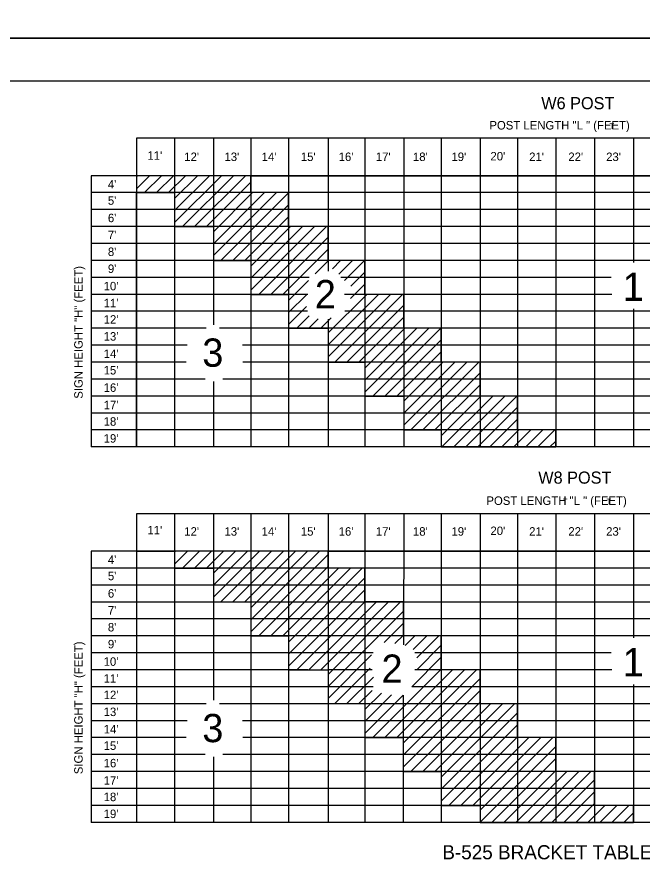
# Model space of a CAD drawing. Extents: x 637580 to 641008, y 294594 to 295782.
# Drawn here: x 639503.7 to 639725, y 294891.9 to 295195.1 of the extents above; entities that cross this region are included whole.
import ezdxf

# ---------------------------------------------------------------- set-up
doc = ezdxf.new("R2010")
doc.units = 0
for name, color, linetype in [('1', 7, 'Continuous'), ('2', 7, 'Continuous'), ('PLT-BNDY', 7, 'Continuous')]:
    doc.layers.add(name, color=color, linetype=linetype)

msp = doc.modelspace()

# ---------------------------------------------------------------- linework, layer by layer
at = {"layer": '1'}
msp.add_line((639302.31, 295172.63), (640088.31, 295172.63), dxfattribs=at)
at = {"layer": '2'}
for p, q in [((639866.29, 295152.27), (639545.88, 295152.27)), ((639545.88, 295152.27), (639545.88, 295043.01)), ((639559.39, 295152.27), (639559.39, 295043.01)), ((639573.15, 295152.27), (639573.15, 295086.26)), ((639586.4, 295152.27), (639586.4, 295043.01)), ((639599.66, 295152.27), (639599.66, 295043.01)), ((639613.67, 295152.27), (639613.67, 295105.22)), ((639626.67, 295152.27), (639626.67, 295043.01)), ((639640.43, 295152.27), (639640.43, 295043.01)), ((639653.69, 295152.27), (639653.69, 295043.01)), ((639667.45, 295152.27), (639667.45, 295043.01)), ((639680.7, 295152.27), (639680.7, 295043.01)), ((639694.21, 295152.27), (639694.21, 295043.01)), ((639707.97, 295152.27), (639707.97, 295043.01)), ((639721.72, 295152.27), (639721.72, 295108.29)), ((639529.84, 295139.01), (639529.84, 295043.01)), ((639866.29, 295139.01), (639529.84, 295139.01)), ((639545.88, 295139.01), (639545.88, 295133.01)), ((639551.38, 295139.01), (639545.88, 295139.01)), ((639545.88, 295138.6), (639546.29, 295139.01)), ((639545.88, 295134.36), (639550.53, 295139.01)), ((639548.78, 295133.01), (639554.78, 295139.01)), ((639586.4, 295139.01), (639551.38, 295139.01)), ((639553.02, 295133.01), (639559.02, 295139.01)), ((639557.26, 295133.01), (639563.26, 295139.01)), ((639559.39, 295130.9), (639567.5, 295139.01)), ((639559.39, 295126.65), (639571.75, 295139.01)), ((639559.39, 295122.41), (639575.99, 295139.01)), ((639562.23, 295121.01), (639580.23, 295139.01)), ((639566.47, 295121.01), (639584.47, 295139.01)), ((639586.4, 295133.01), (639586.4, 295139.01)), ((639586.4, 295139.01), (639827.27, 295139.01)), ((639570.72, 295121.01), (639586.4, 295136.7)), ((639827.27, 295133.01), (639529.84, 295133.01)), ((639545.88, 295043.01), (639545.88, 295133.01)), ((639545.88, 295133.01), (639559.39, 295133.01)), ((639545.88, 295133.01), (639559.39, 295133.01)), ((639559.39, 295133.01), (639559.39, 295121.01)), ((639559.39, 295133.01), (639559.39, 295121.01)), ((639573.15, 295119.2), (639586.96, 295133.01)), ((639573.15, 295114.95), (639591.2, 295133.01)), ((639573.15, 295110.71), (639595.44, 295133.01)), ((639575.69, 295109.01), (639599.66, 295132.98)), ((639599.66, 295133.01), (639586.4, 295133.01)), ((639599.66, 295121.01), (639599.66, 295133.01)), ((639840.28, 295127.01), (639529.84, 295127.01)), ((639579.93, 295109.01), (639599.66, 295128.74)), ((639584.17, 295109.01), (639599.66, 295124.5)), ((639840.28, 295121.01), (639529.84, 295121.01)), ((639559.39, 295121.01), (639573.15, 295121.01)), ((639559.39, 295121.01), (639573.15, 295121.01)), ((639573.15, 295121.01), (639573.15, 295109.01)), ((639573.15, 295121.01), (639573.15, 295109.01)), ((639586.4, 295107), (639600.41, 295121.01)), ((639586.4, 295102.75), (639604.66, 295121.01)), ((639586.4, 295098.51), (639608.9, 295121.01)), ((639589.14, 295097.01), (639613.14, 295121.01)), ((639613.67, 295121.01), (639599.66, 295121.01)), ((639613.67, 295109.01), (639613.67, 295121.01)), ((639853.28, 295115.01), (639529.84, 295115.01)), ((639593.39, 295097.01), (639613.67, 295117.29)), ((639597.63, 295097.01), (639613.67, 295113.05)), ((639853.28, 295109.01), (639529.84, 295109.01)), ((639573.15, 295109.01), (639586.4, 295109.01)), ((639573.15, 295109.01), (639586.4, 295109.01)), ((639586.4, 295109.01), (639586.4, 295097.01)), ((639586.4, 295109.01), (639586.4, 295097.01)), ((639609.14, 295104.28), (639613.87, 295109.01)), ((639626.67, 295109.01), (639613.67, 295109.01)), ((639615.2, 295106.09), (639618.11, 295109.01)), ((639617.45, 295104.1), (639622.36, 295109.01)), ((639619.51, 295101.92), (639626.6, 295109.01)), ((639626.67, 295097.01), (639626.67, 295109.01)), ((639607.01, 295103.01), (639529.84, 295103.01)), ((639713.86, 295103.01), (639618.23, 295103.01)), ((639621.73, 295099.9), (639626.67, 295104.84)), ((639599.66, 295094.8), (639606.72, 295101.86)), ((639621.58, 295095.51), (639626.67, 295100.6)), ((639606.46, 295097.01), (639529.84, 295097.01)), ((639586.4, 295097.01), (639599.66, 295097.01)), ((639586.4, 295097.01), (639599.66, 295097.01)), ((639599.66, 295097.01), (639599.66, 295085.01)), ((639599.66, 295097.01), (639599.66, 295085.01)), ((639599.66, 295090.56), (639606.11, 295097.01)), ((639613.67, 295083.35), (639627.33, 295097.01)), ((639613.67, 295079.11), (639631.57, 295097.01)), ((639613.67, 295074.86), (639635.81, 295097.01)), ((639616.05, 295073.01), (639640.05, 295097.01)), ((639714.04, 295097.01), (639619.44, 295097.01)), ((639640.43, 295097.01), (639626.67, 295097.01)), ((639640.43, 295085.01), (639640.43, 295097.01)), ((639606.35, 295091.01), (639529.84, 295091.01)), ((639599.66, 295086.31), (639606.09, 295092.74)), ((639866.29, 295091.01), (639619.55, 295091.01)), ((639620.3, 295073.01), (639640.43, 295093.14)), ((639721.72, 295091.85), (639721.72, 295043.01)), ((639602.6, 295085.01), (639607.03, 295089.44)), ((639606.84, 295085.01), (639610.13, 295088.3)), ((639611.08, 295085.01), (639614.79, 295088.71)), ((639613.67, 295088.28), (639613.67, 295043.01)), ((639624.54, 295073.01), (639640.43, 295088.9)), ((639570.59, 295085.01), (639529.84, 295085.01)), ((639866.29, 295085.01), (639575.26, 295085.01)), ((639599.66, 295085.01), (639613.67, 295085.01)), ((639599.66, 295085.01), (639613.67, 295085.01)), ((639613.67, 295085.01), (639613.67, 295073.01)), ((639613.67, 295085.01), (639613.67, 295073.01)), ((639626.67, 295070.9), (639640.78, 295085.01)), ((639626.67, 295066.66), (639645.02, 295085.01)), ((639626.67, 295062.42), (639649.27, 295085.01)), ((639629.51, 295061.01), (639653.51, 295085.01)), ((639653.69, 295085.01), (639640.43, 295085.01)), ((639653.69, 295073.01), (639653.69, 295085.01)), ((639563.85, 295079.01), (639529.84, 295079.01)), ((639866.29, 295079.01), (639583.36, 295079.01)), ((639633.75, 295061.01), (639653.69, 295080.94)), ((639638, 295061.01), (639653.69, 295076.7)), ((639563.44, 295073.01), (639529.84, 295073.01)), ((639866.29, 295073.01), (639583.5, 295073.01)), ((639613.67, 295073.01), (639626.67, 295073.01)), ((639613.67, 295073.01), (639626.67, 295073.01)), ((639626.67, 295073.01), (639626.67, 295061.01)), ((639626.67, 295073.01), (639626.67, 295061.01)), ((639640.43, 295059.2), (639654.24, 295073.01)), ((639640.43, 295054.96), (639658.48, 295073.01)), ((639640.43, 295050.72), (639662.72, 295073.01)), ((639642.97, 295049.01), (639666.97, 295073.01)), ((639667.45, 295073.01), (639653.69, 295073.01)), ((639667.45, 295061.01), (639667.45, 295073.01)), ((639647.21, 295049.01), (639667.45, 295069.25)), ((639570.17, 295067.01), (639529.84, 295067.01)), ((639573.15, 295066.19), (639573.15, 295043.01)), ((639866.29, 295067.01), (639576.49, 295067.01)), ((639651.45, 295049.01), (639667.45, 295065)), ((639866.29, 295061.01), (639529.84, 295061.01)), ((639626.67, 295061.01), (639640.43, 295061.01)), ((639626.67, 295061.01), (639640.43, 295061.01)), ((639640.43, 295061.01), (639640.43, 295049.01)), ((639640.43, 295061.01), (639640.43, 295049.01)), ((639653.69, 295047), (639667.69, 295061.01)), ((639653.94, 295043.01), (639671.94, 295061.01)), ((639658.18, 295043.01), (639676.18, 295061.01)), ((639662.42, 295043.01), (639680.42, 295061.01)), ((639680.7, 295061.01), (639667.45, 295061.01)), ((639680.7, 295049.01), (639680.7, 295061.01)), ((639666.66, 295043.01), (639680.7, 295057.05)), ((639866.29, 295055.01), (639529.84, 295055.01)), ((639670.91, 295043.01), (639680.7, 295052.8)), ((639866.29, 295049.01), (639529.84, 295049.01)), ((639640.43, 295049.01), (639653.69, 295049.01)), ((639640.43, 295049.01), (639653.69, 295049.01)), ((639653.69, 295049.01), (639653.69, 295043.01)), ((639653.69, 295049.01), (639653.69, 295043.01)), ((639675.15, 295043.01), (639681.15, 295049.01)), ((639679.39, 295043.01), (639685.39, 295049.01)), ((639694.21, 295049.01), (639680.7, 295049.01)), ((639683.64, 295043.01), (639689.64, 295049.01)), ((639687.88, 295043.01), (639693.88, 295049.01)), ((639694.21, 295043.01), (639694.21, 295049.01)), ((639692.12, 295043.01), (639694.21, 295045.1)), ((639866.29, 295043.01), (639529.84, 295043.01)), ((639653.69, 295043.01), (639545.88, 295043.01)), ((639653.69, 295043.01), (639694.21, 295043.01)), ((639866.29, 295043.01), (639694.21, 295043.01)), ((639866.29, 295019.39), (639545.88, 295019.39)), ((639545.88, 295019.39), (639545.88, 294910.13)), ((639559.39, 295019.39), (639559.39, 294910.13)), ((639573.15, 295019.39), (639573.15, 294953.39)), ((639586.4, 295019.39), (639586.4, 294910.13)), ((639599.66, 295019.39), (639599.66, 294910.13)), ((639613.67, 295019.39), (639613.67, 294910.13)), ((639626.67, 295019.39), (639626.67, 294910.13)), ((639640.43, 295019.39), (639640.33, 294973.02)), ((639653.69, 295019.39), (639653.69, 294910.13)), ((639667.45, 295019.39), (639667.45, 294910.13)), ((639680.7, 295019.39), (639680.7, 294910.13)), ((639694.21, 295019.39), (639694.21, 294910.13)), ((639707.97, 295019.39), (639707.97, 294910.13)), ((639721.72, 295019.39), (639721.72, 294975.41)), ((639529.84, 295006.13), (639529.84, 294910.13)), ((639866.29, 295006.13), (639529.84, 295006.13)), ((639545.88, 295006.13), (639559.39, 295006.13)), ((639545.88, 295005.73), (639546.29, 295006.13)), ((639559.4, 295006.13), (639559.4, 295000.11)), ((639564.96, 295006.13), (639559.4, 295006.13)), ((639559.4, 295005.79), (639559.74, 295006.13)), ((639559.4, 295001.55), (639563.99, 295006.13)), ((639562.21, 295000.11), (639568.23, 295006.13)), ((639613.67, 295006.13), (639564.96, 295006.13)), ((639566.45, 295000.11), (639572.47, 295006.13)), ((639570.69, 295000.11), (639576.72, 295006.13)), ((639573.13, 294998.31), (639580.96, 295006.13)), ((639573.13, 294994.07), (639585.2, 295006.13)), ((639573.13, 294989.82), (639589.44, 295006.13)), ((639575.69, 294988.14), (639593.69, 295006.13)), ((639579.94, 294988.14), (639597.93, 295006.13)), ((639584.18, 294988.14), (639602.17, 295006.13)), ((639586.4, 294986.12), (639606.41, 295006.13)), ((639586.4, 294981.88), (639610.66, 295006.13)), ((639613.66, 295000.13), (639613.67, 295006.13)), ((639613.67, 295006.13), (639827.27, 295006.13)), ((639586.4, 294977.63), (639613.66, 295004.9)), ((639827.27, 295000.13), (639529.84, 295000.13)), ((639559.4, 295000.11), (639573.13, 295000.11)), ((639573.13, 295000.11), (639573.13, 294988.14)), ((639589.14, 294976.13), (639613.64, 295000.63)), ((639593.38, 294976.13), (639617.31, 295000.06)), ((639597.63, 294976.13), (639621.55, 295000.06)), ((639599.68, 294973.94), (639625.79, 295000.05)), ((639626.64, 295000.13), (639613.66, 295000.13)), ((639626.67, 294988.14), (639626.64, 295000.13)), ((639599.68, 294969.7), (639626.7, 294996.72)), ((639840.28, 294994.13), (639529.84, 294994.13)), ((639599.68, 294965.45), (639626.68, 294992.46)), ((639840.28, 294988.13), (639529.84, 294988.13)), ((639573.13, 294988.14), (639586.4, 294988.14)), ((639586.4, 294988.14), (639586.4, 294976.13)), ((639602.57, 294964.11), (639626.67, 294988.2)), ((639606.82, 294964.11), (639630.85, 294988.14)), ((639611.06, 294964.11), (639635.09, 294988.14)), ((639613.66, 294962.46), (639639.34, 294988.14)), ((639640.36, 294988.15), (639626.67, 294988.14)), ((639640.36, 294976.13), (639640.36, 294988.15)), ((639613.66, 294958.22), (639640.36, 294984.93)), ((639853.28, 294982.13), (639529.84, 294982.13)), ((639633.46, 294973.79), (639640.36, 294980.68)), ((639853.28, 294976.13), (639529.84, 294976.13)), ((639586.4, 294976.13), (639599.68, 294976.13)), ((639599.68, 294976.13), (639599.68, 294964.11)), ((639637.33, 294973.41), (639640.36, 294976.44)), ((639653.68, 294976.13), (639640.36, 294976.13)), ((639640.89, 294972.73), (639644.32, 294976.15)), ((639643.75, 294971.34), (639648.56, 294976.15)), ((639645.05, 294968.4), (639652.8, 294976.15)), ((639653.68, 294964.11), (639653.68, 294976.13)), ((639645.02, 294964.13), (639653.7, 294972.81)), ((639613.67, 294970.13), (639529.84, 294970.13)), ((639613.66, 294953.98), (639629.09, 294969.41)), ((639629.63, 294970.13), (639613.67, 294970.13)), ((639713.86, 294970.13), (639644.42, 294970.13)), ((639643.27, 294958.13), (639653.7, 294968.56)), ((639606.46, 294964.13), (639529.84, 294964.13)), ((639599.68, 294964.11), (639613.66, 294964.11)), ((639613.66, 294964.11), (639613.66, 294952.18)), ((639629.25, 294964.13), (639613.67, 294964.13)), ((639616.1, 294952.18), (639628.59, 294964.67)), ((639629.52, 294940.14), (639653.7, 294964.32)), ((639633.76, 294940.14), (639657.71, 294964.09)), ((639638.01, 294940.14), (639661.95, 294964.09)), ((639640.28, 294938.17), (639666.2, 294964.09)), ((639714.04, 294964.13), (639644.42, 294964.13)), ((639667.45, 294964.11), (639653.68, 294964.11)), ((639667.46, 294952.11), (639667.45, 294964.11)), ((639620.34, 294952.18), (639629.7, 294961.53)), ((639640.28, 294933.93), (639667.46, 294961.11)), ((639613.67, 294958.13), (639529.84, 294958.13)), ((639629.6, 294958.13), (639613.67, 294958.13)), ((639866.29, 294958.13), (639643.27, 294958.13)), ((639721.72, 294958.97), (639721.72, 294910.13)), ((639624.58, 294952.18), (639629.28, 294956.87)), ((639626.69, 294950.04), (639632.53, 294955.88)), ((639626.69, 294945.8), (639636.15, 294955.26)), ((639626.69, 294941.55), (639640.29, 294955.16)), ((639640.29, 294955.16), (639640.19, 294910.13)), ((639640.28, 294929.69), (639667.46, 294956.87)), ((639570.59, 294952.13), (639529.84, 294952.13)), ((639866.29, 294952.13), (639575.26, 294952.13)), ((639613.66, 294952.18), (639626.69, 294952.18)), ((639626.69, 294952.18), (639626.69, 294940.14)), ((639642.97, 294928.13), (639667.46, 294952.63)), ((639647.21, 294928.13), (639671.19, 294952.11)), ((639651.45, 294928.13), (639675.43, 294952.11)), ((639653.69, 294926.13), (639679.67, 294952.11)), ((639680.71, 294952.11), (639667.46, 294952.11)), ((639680.71, 294940.15), (639680.71, 294952.11)), ((639653.69, 294921.88), (639680.71, 294948.91)), ((639563.85, 294946.13), (639529.84, 294946.13)), ((639866.29, 294946.13), (639583.36, 294946.13)), ((639653.69, 294917.64), (639680.71, 294944.67)), ((639563.44, 294940.13), (639529.84, 294940.13)), ((639866.29, 294940.13), (639583.5, 294940.13)), ((639626.69, 294940.14), (639640.28, 294940.14)), ((639640.28, 294940.14), (639640.28, 294928.13)), ((639656.44, 294916.15), (639680.71, 294940.42)), ((639660.68, 294916.15), (639684.68, 294940.15)), ((639664.92, 294916.15), (639688.93, 294940.15)), ((639667.45, 294914.43), (639693.17, 294940.16)), ((639694.21, 294940.13), (639680.71, 294940.15)), ((639694.22, 294928.14), (639694.21, 294940.13)), ((639667.45, 294910.19), (639694.24, 294936.98)), ((639570.17, 294934.13), (639529.84, 294934.13)), ((639573.15, 294933.32), (639573.15, 294910.13)), ((639866.29, 294934.13), (639576.49, 294934.13)), ((639671.63, 294910.13), (639694.25, 294932.75)), ((639866.29, 294928.13), (639529.84, 294928.13)), ((639640.28, 294928.13), (639653.69, 294928.13)), ((639653.69, 294928.13), (639653.69, 294916.15)), ((639675.88, 294910.13), (639694.21, 294928.47)), ((639680.12, 294910.13), (639698.11, 294928.13)), ((639684.36, 294910.13), (639702.35, 294928.12)), ((639688.6, 294910.13), (639706.58, 294928.11)), ((639694.29, 294928.13), (639694.22, 294928.14)), ((639707.96, 294928.14), (639694.29, 294928.13)), ((639707.97, 294916.13), (639707.96, 294928.14)), ((639692.84, 294910.13), (639707.95, 294925.24)), ((639866.29, 294922.13), (639529.84, 294922.13)), ((639697.09, 294910.13), (639707.93, 294920.98)), ((639866.29, 294916.13), (639529.84, 294916.13)), ((639653.69, 294916.15), (639667.45, 294916.15)), ((639667.45, 294916.15), (639667.45, 294910.13)), ((639701.33, 294910.13), (639707.97, 294916.77)), ((639705.57, 294910.13), (639711.6, 294916.15)), ((639709.81, 294910.13), (639715.84, 294916.15)), ((639714.05, 294910.13), (639720.06, 294916.13)), ((639718.3, 294910.13), (639721.72, 294913.55)), ((639866.29, 294910.13), (639529.84, 294910.13)), ((639667.45, 294910.13), (639545.88, 294910.13)), ((639667.45, 294910.13), (639721.72, 294910.13)), ((639866.29, 294910.13), (639721.72, 294910.13))]:
    msp.add_line(p, q, dxfattribs=at)
msp.add_lwpolyline([(639721.72, 294910.13), (639721.72, 294910.18), (639721.72, 294916.14), (639707.97, 294916.13)], dxfattribs=at)
at = {"layer": 'PLT-BNDY'}
for points in [[(639262.31, 295781.63), (640103.31, 295781.63), (640103.31, 295187.63), (639262.31, 295187.63)], [(639262.31, 295187.63), (640103.31, 295187.63), (640103.31, 294593.63), (639262.31, 294593.63)]]:
    msp.add_lwpolyline(points, close=True, dxfattribs=at)

# ---------------------------------------------------------------- texts
at = {"layer": '2'}
for s, height, p in [('W6 POST', 4.3, (639689.09, 295162.53)), ('POST LENGTH "L " (FEET)', 3, (639670.74, 295155.36)), ('T', 2, (639713.26, 295155.53)), ("11'", 3, (639549.76, 295144.65)), ("12'", 3, (639562.8, 295144.2)), ("13'", 3, (639577.03, 295144.2)), ("14'", 3, (639590.17, 295144.2)), ("15'", 3, (639604.03, 295144.2)), ("16'", 3, (639617.42, 295144.2)), ("17'", 3, (639630.56, 295144.2)), ("18'", 3, (639643.7, 295144.2)), ("19'", 3, (639657.32, 295144.2)), ("20'", 3, (639671.11, 295144.41)), ("21'", 3, (639684.81, 295144.2)), ("22'", 3, (639698.67, 295144.2)), ("23'", 3, (639712.05, 295144.2)), ("4'", 3, (639535.78, 295134.48)), ("5'", 3, (639535.78, 295128.72)), ("6'", 3, (639535.78, 295122.56)), ("7'", 3, (639535.78, 295116.57)), ("8'", 3, (639535.78, 295110.58)), ("9'", 3, (639535.78, 295104.59)), ('1', 10, (639717.89, 295094.72)), ("10'", 3, (639534.28, 295098.43)), ('2', 10, (639609, 295092.1)), ("11'", 3, (639534.28, 295092.44)), ("12'", 3, (639534.28, 295086.63)), ("13'", 3, (639534.28, 295080.64)), ('3', 10, (639569.18, 295071.39)), ("14'", 3, (639534.28, 295074.47)), ("15'", 3, (639534.28, 295068.66)), ("16'", 3, (639534.28, 295062.5)), ("17'", 3, (639534.28, 295056.33)), ("18'", 3, (639534.28, 295050.52)), ("19'", 3, (639534.28, 295044.53)), ('W8 POST', 4.3, (639688.03, 295030.01)), ('POST LENGTH "L " (FEET)', 3, (639669.69, 295022.49)), ('T', 2, (639696.71, 295022.66)), ('T', 2, (639712.21, 295022.66)), ("11'", 3, (639549.76, 295012.07)), ("12'", 3, (639562.8, 295011.61)), ("13'", 3, (639577.03, 295011.61)), ("14'", 3, (639590.17, 295011.61)), ("15'", 3, (639604.03, 295011.61)), ("16'", 3, (639617.42, 295011.61)), ("17'", 3, (639630.56, 295011.61)), ("18'", 3, (639643.7, 295011.61)), ("19'", 3, (639657.32, 295011.61)), ("20'", 3, (639671.11, 295011.83)), ("21'", 3, (639684.81, 295011.61)), ("22'", 3, (639698.67, 295011.61)), ("23'", 3, (639712.05, 295011.61)), ('2', 10, (639632.59, 294959.54)), ('1', 10, (639717.89, 294961.85)), ("10'", 3, (639534.28, 294965.55)), ("11'", 3, (639534.28, 294959.56)), ("12'", 3, (639534.28, 294953.75)), ("13'", 3, (639534.28, 294947.76)), ('3', 10, (639569.18, 294938.52)), ("14'", 3, (639534.28, 294941.6)), ("15'", 3, (639534.28, 294935.79)), ("16'", 3, (639534.28, 294929.62)), ("17'", 3, (639534.28, 294923.46)), ("18'", 3, (639534.28, 294917.65)), ("19'", 3, (639534.28, 294911.66)), ('B-525 BRACKET TABLES', 5, (639654.09, 294897.07))]:
    msp.add_text(s, height=height, dxfattribs=at).set_placement(p)
for s, rotation, p in [('SIGN HEIGHT "H" (FEET)', 90, (639526.87, 295060.07)), ("4'", 360, (639535.78, 295001.61)), ("5'", 360, (639535.78, 294995.85)), ("6'", 360, (639535.78, 294989.68)), ("7'", 360, (639535.78, 294983.69)), ("8'", 360, (639535.78, 294977.71)), ('SIGN HEIGHT "H" (FEET)', 90, (639526.87, 294927.19)), ("9'", 360, (639535.78, 294971.72))]:
    msp.add_text(s, height=3, rotation=rotation, dxfattribs=at).set_placement(p)

doc.saveas('drawing.dxf')
